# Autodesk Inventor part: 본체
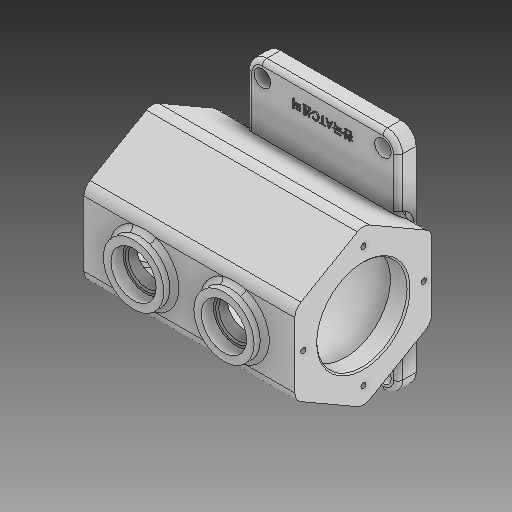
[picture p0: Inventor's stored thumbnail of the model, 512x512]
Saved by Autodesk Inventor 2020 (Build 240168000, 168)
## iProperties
Created: 2021-06
Part Number: 본체
Material: 일반
Document SubType Name: Modeling
Designer: 605-01
Density: 1 g/cm^3
Appearance: 기본값
Author: 605-01
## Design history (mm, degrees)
sketch "스케치1"
  geometry: L1 (-50, -75)-(50, -75); L2 (50, -75)-(50, 75); L3 (50, 75)-(-50, 75); L4 (-50, 75)-(-50, -75); L5 (-50, -75)-(50, 75); L6 (50, -75)-(-50, 75); 1 further point
  constraints: 12 end point, 2 midpoint, 2 parallel, 1 horizontal, 1 perpendicular
  dimensions: "d0" = 100 distance of L3.end L2.end; "d1" = 150 distance of L2.end L1.end
extrude "돌출1" new body sketch "스케치1" distance "d2" = 12; taper "d3" = 0 deg
node "작업 평면3"
sketch "스케치5" dims "d15" = 105
  geometry: L1 (75, 0)-(-75, 0) reference; L2 (-75, 0)-(-75, 12) reference; L3 (75, 12)-(-75, 12) reference; L4 (75, 0)-(75, 12) reference; L5 (-52.5, 50)-(-26.25, 95.466); L6 (-26.25, 95.466)-(26.25, 95.466); L7 (26.25, 95.466)-(52.5, 50); L8 (52.5, 50)-(26.25, 4.534); L9 (26.25, 4.534)-(-26.25, 4.534); L10 (-26.25, 4.534)-(-52.5, 50); 4 further points
  constraints: 12 end point, 1 coincident, 1 horizontal alignment, 1 midpoint, 1 vertical alignment, 15 other
  dimensions: "d16" = 50 distance from line of L1 point (0, 50); "d17" = 50 distance from line of L1 L7.end
extrude "돌출2" join sketch "스케치5" distance "d18" = 140; taper "d19" = 0 deg
sketch "스케치6"
  geometry: L1 (75, 50)-(75, 95.466) reference; L2 (75, 95.466)-(-65, 95.466) reference; L3 (-65, 50)-(-65, 95.466) reference; L4 (75, 50)-(-65, 50) reference; L5 (-50, 12)-(-50, 4.534) reference; L6 (50, 12)-(-50, 12) reference; L7 (50, 4.534)-(50, 12) reference; L8 (75, 4.534)-(50, 4.534) reference; L9 (75, 4.534)-(75, 50) reference; L10 (75, 50)-(-65, 50) reference; L11 (-65, 4.534)-(-65, 50) reference; L12 (-50, 4.534)-(-65, 4.534) reference; L13 (75, 80)-(63, 80); L14 (63, 80)-(63, 82.5); L15 (58, 87.5)-(-48, 87.5); L16 (-53, 82.5)-(-53, 80); L17 (-53, 80)-(-65, 80); L18 (75, 80)-(75, 50); L19 (75, 50)-(-65, 50); L20 (-65, 50)-(-65, 80); L21 (-50, 0)-(50, 0) reference; A1 r 5 centre (58, 82.5) between (63, 82.5) and (58, 87.5); A2 r 5 centre (-48, 82.5) between (-48, 87.5) and (-53, 82.5); 1 further point
  constraints: 16 end point, 6 point on line, 4 point on circle, 4 tangent, 3 perpendicular, 2 centre point, 2 horizontal, 1 collinear, 1 equal radius
  dimensions: "d20" = 12 distance of L13.start L13.end; "d21" = 12 distance of L16.end L17.end; "d22" = 50 distance from line of L19.end L21; "d23" = 5 radius of A1; "d24" = 75 diameter of L15 L10; "d25" = 60 diameter of L13 L4
revolve "회전1" sketch "스케치6" stored, may be unused: angle "d26" = 90 deg
node "작업 평면4"
sketch "스케치8"
  geometry: L1 (-75, 26.25)-(-75, -26.25) reference; C1 r 20 at (-35, 0); C2 r 20 at (25, 0); 1 further point
  constraints: 2 centre point, 2 horizontal alignment
  dimensions: "d36" = 40 diameter of C1; "d37" = 40 diameter of C2; "d38" = 40 distance from line of C1.centre L1; "d39" = 60 distance of C2.centre C1.centre
extrude "돌출3" join sketch "스케치8" stored distance "d40" = 140; taper "d41" = 0 deg
sketch "스케치9"
  geometry: C1 r 20 at (0, 0) reference; C2 r 20 at (60, 0) reference; 4 further points
  constraints: 3 coincident
hole "구멍1" sketch "스케치9" at (0, 0), (60, 0) diameter "d42" = 25; stored, may be unused: countersink angle "d46" = 90 deg, drill point angle "d48" = 0 deg; dims "d43" = 6, "d44" = 30, "d45" = 8, "d47" = 8
chamfer "모따기1" distance "d49" = 1; stored, may be unused: second distance "d50" = 2, angle "d51" = 45 deg
sketch "스케치10"
  geometry: L1 (50, 0)-(78.284, 28.284); L2 (50, 0)-(90, 0); C1 r 30 at (50, 0) reference; A1 r 40 centre (50, 0) between (78.284, 28.284) and (90, 0); 2 further points
  constraints: 4 end point, 2 coincident, 2 point on circle, 1 centre point, 1 horizontal
  dimensions: "d52" = 80 diameter of A1; "d53" = 45 deg angle of L2 L1
hole "구멍2" sketch "스케치10" at (78.284, 28.284) diameter "d54" = 3.45873; stored, may be unused: countersink angle "d58" = 90 deg, drill point angle "d60" = 118 deg; dims "d55" = 8, "d56" = 30, "d57" = 8, "d59" = 10
sketch "스케치11" dims "d64" = 80
  geometry: L1 (-50, 0)-(-90, 0); C1 r 31 at (-50, 0) reference; 2 further points
  constraints: 2 coincident, 2 end point, 1 horizontal, 1 horizontal alignment, 2 other
hole "구멍3" sketch "스케치11" at (-90, 0) diameter "d65" = 3.45873; stored, may be unused: countersink angle "d69" = 90 deg, drill point angle "d71" = 118 deg; dims "d66" = 8, "d67" = 30, "d68" = 8, "d70" = 10
fillet "모깎기1" dims "d75" = 8
fillet "모깎기2" dims "d76" = 10
sketch "스케치12"
  geometry: A1 r 10 centre (-40, -65) between (-50, -65) and (-40, -75) reference; A2 r 10 centre (40, -65) between (40, -75) and (50, -65) reference; A3 r 10 centre (40, 65) between (50, 65) and (40, 75) reference; A4 r 10 centre (-40, 65) between (-40, 75) and (-50, 65) reference; 5 further points
  constraints: 4 coincident
hole "구멍4" sketch "스케치12" at (-40, -65), (40, -65), (40, 65), (-40, 65) diameter "d77" = 11; stored, may be unused: countersink angle "d81" = 90 deg, drill point angle "d83" = 118 deg; dims "d78" = 8, "d79" = 30, "d80" = 8, "d82" = 10
fillet "모깎기3" dims "d84" = 3
sketch "스케치13"
  geometry: L1 (20.739, 57.998)-(-20.739, 57.998); L2 (-20.739, 57.998)-(-20.739, 64.002); L3 (-20.739, 64.002)-(20.739, 64.002); L4 (20.739, 64.002)-(20.739, 57.998); L5 (20.739, 57.998)-(-20.739, 64.002); L6 (-50, 65)-(-50, 32.293) reference; L7 (40, 75)-(-40, 75) reference; 2 further points
  constraints: 2 end point, 1 midpoint, 2 other
  dimensions: "d85" = 50 distance from line of point (0, 61) L6; "d86" = 14 distance from line of point (0, 61) L7
feature "엠보싱1" sketch "스케치13" dims "d87" = 0.5, "d88" = 0
node "솔리드1"
pattern_circular "원형 패턴1" dims angle "d62" = 360 deg
pattern_circular "원형 패턴2" dims angle "d73" = 360 deg
node "투영된 루프1"
node "투영된 루프2"
node "투영된 루프3"
feature "A9D066F2-1C7D-4E18-AEED-F7BC21143FA4" dims "d77" = 11, "d78" = 8, "d79" = 30, "d80" = 8, "d81" = 90 deg, "d82" = 10, "d83" = 118 deg
other parameters: "d14" = -75, "d31" = 102.5
